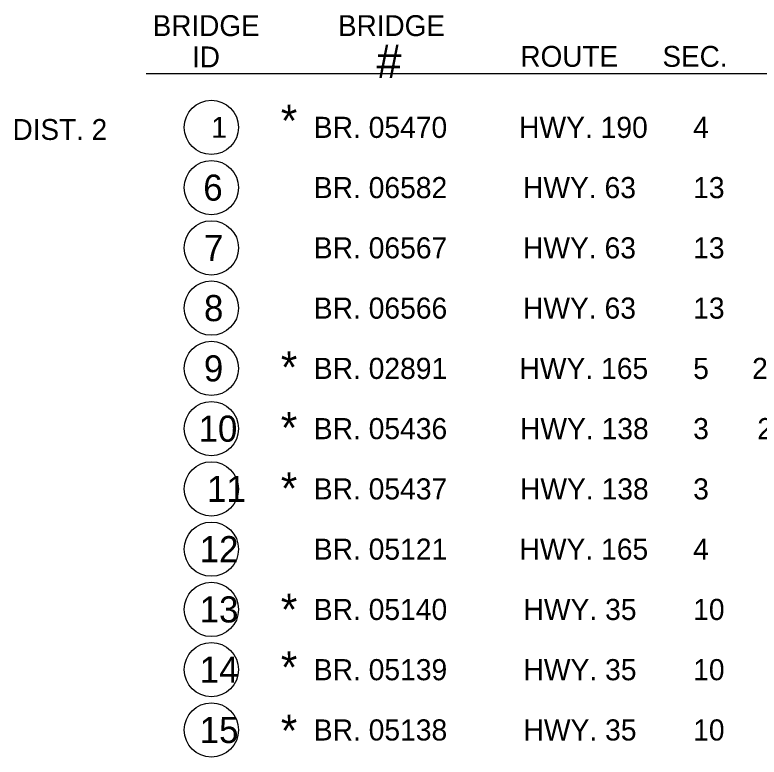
# Model space of a CAD drawing. Extents: x 1927831 to 1930787, y 596452 to 597699.
# Drawn here: x 1927842.5 to 1928053.9, y 596673.4 to 596884.2 of the extents above; entities that cross this region are included whole.
import ezdxf

# ---------------------------------------------------------------- set-up
doc = ezdxf.new("R2010")
doc.units = 0
doc.layers.add('Default', color=7, linetype='Continuous')
doc.layers.add('R_Annotation', color=7, linetype='Continuous')

msp = doc.modelspace()

# ---------------------------------------------------------------- linework, layer by layer
at = {"layer": 'Default'}
for centre in [(1927898.29, 596852.3), (1927898.29, 596835.19), (1927898.29, 596818.07), (1927898.29, 596800.95), (1927898.29, 596783.83), (1927898.29, 596766.72), (1927898.29, 596749.6), (1927898.29, 596732.48), (1927898.29, 596715.36), (1927898.29, 596698.26), (1927898.29, 596681.13)]:
    msp.add_circle(centre, 7.71, dxfattribs=at)
at = {"layer": 'R_Annotation'}
msp.add_line((1927879.74, 596867.56), (1928183.67, 596867.56), dxfattribs=at)

# ---------------------------------------------------------------- texts
for s, height, p in [('BRIDGE ', 5.929, (1927881.62, 596878.23)), ('BRIDGE ', 5.929, (1927934.26, 596878.23)), ('ID', 5.929, (1927892.81, 596869.34)), ('#', 9.5, (1927945.24, 596866.36)), ('ROUTE', 5.929, (1927986.1, 596869.5)), ('SEC.', 5.929, (1928026.44, 596869.5)), ('*', 9, (1927918.02, 596849.71)), ('DIST. 2', 5.929, (1927841.82, 596848.73)), ('1', 5.93, (1927898.29, 596849.34)), ('BR. 05470', 6, (1927927.38, 596849.3)), ('HWY. 190', 6, (1927985.71, 596849.3)), ('4', 6, (1928035.17, 596849.3)), ('6', 7.41, (1927895.99, 596831.48)), ('BR. 06582', 6, (1927927.38, 596832.19)), ('HWY. 63', 6, (1927986.82, 596832.19)), ('13', 6, (1928035.17, 596832.19)), ('7', 7.41, (1927896.19, 596814.36)), ('BR. 06567', 6, (1927927.38, 596815.07)), ('HWY. 63', 6, (1927986.82, 596815.07)), ('13', 6, (1928035.17, 596815.07)), ('8', 7.41, (1927896.19, 596797.25)), ('BR. 06566', 6, (1927927.38, 596797.95)), ('HWY. 63', 6, (1927986.82, 596797.95)), ('13', 6, (1928035.17, 596797.95)), ('*', 9, (1927918.02, 596779.68)), ('9', 7.41, (1927896.16, 596780.13)), ('BR. 02891', 6, (1927927.38, 596780.83)), ('HWY. 165', 6, (1927985.83, 596780.83)), ('5', 6, (1928035.17, 596780.83)), ('28.572', 6, (1928051.91, 596780.83)), ('*', 9, (1927918.02, 596762.48)), ('10', 7.412, (1927894.64, 596763.01)), ('BR. 05436', 6, (1927927.38, 596763.72)), ('HWY. 138', 6, (1927985.97, 596763.72)), ('3', 6, (1928035.17, 596763.72)), ('20.931', 6, (1928053.37, 596763.72)), ('*', 9, (1927918.02, 596745.27)), ('11', 7.412, (1927897.07, 596745.89)), ('BR. 05437', 6, (1927927.38, 596746.6)), ('HWY. 138', 6, (1927985.97, 596746.6)), ('3', 6, (1928035.17, 596746.6)), ('12', 7.412, (1927894.97, 596728.78)), ('BR. 05121', 6, (1927927.38, 596729.48)), ('HWY. 165', 6, (1927985.83, 596729.48)), ('4', 6, (1928035.17, 596729.48)), ('13', 7.412, (1927894.97, 596711.66)), ('*', 9, (1927918.02, 596710.86)), ('BR. 05140', 6, (1927927.38, 596712.36)), ('HWY. 35', 6, (1927986.97, 596712.36)), ('10', 6, (1928035.17, 596712.36)), ('*', 9, (1927918.02, 596694.46)), ('14', 7.412, (1927894.97, 596694.56)), ('BR. 05139', 6, (1927927.38, 596695.25)), ('HWY. 35', 6, (1927986.97, 596695.25)), ('10', 6, (1928035.17, 596695.25)), ('15', 7.412, (1927894.97, 596677.42)), ('*', 9, (1927918.02, 596676.45)), ('BR. 05138', 6, (1927927.38, 596678.13)), ('HWY. 35', 6, (1927986.97, 596678.13)), ('10', 6, (1928035.17, 596678.13))]:
    msp.add_text(s, height=height, rotation=360, dxfattribs=at).set_placement(p)

doc.saveas('drawing.dxf')
